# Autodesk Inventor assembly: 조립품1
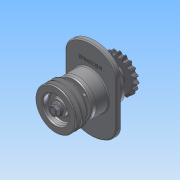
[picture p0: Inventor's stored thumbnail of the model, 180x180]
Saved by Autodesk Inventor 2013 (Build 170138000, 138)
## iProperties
Created: 2015-02
Part Number: 조립품1
Document SubType Name: Assembly
Designer: Administrator
Author: Administrator
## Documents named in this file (11)
- C:\Documents and Settings\Administrator\바탕 화면\새 폴더\조립품1.iam
- C:\Documents and Settings\Administrator\바탕 화면\새 폴더\1.본체.ipt
- C:\Documents and Settings\Administrator\바탕 화면\새 폴더\450207V1017\2-커버.ipt
- C:\Documents and Settings\Administrator\바탕 화면\새 폴더\450207V1017\3-축.ipt
- C:\Documents and Settings\Administrator\바탕 화면\새 폴더\450207V1017\5-체인 스프로킷.ipt
- C:\Documents and Settings\Administrator\바탕 화면\새 폴더\450207V1017\4-V벨트풀리.ipt
- C:\Documents and Settings\Administrator\바탕 화면\새 폴더\450207V1017\6-베어링 6206.ipt
- C:\Documents and Settings\Administrator\바탕 화면\새 폴더\450207V1017\7-부시.ipt
- C:\Documents and Settings\Administrator\바탕 화면\새 폴더\450207V1017\8-오일실 30x42.ipt
- C:\Documents and Settings\Administrator\바탕 화면\새 폴더\450207V1017\11-키 6x6.ipt
- C:\Documents and Settings\Administrator\바탕 화면\새 폴더\450207V1017\9-M16-너트.ipt
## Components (15 placed, 10 different names)
1. 1.본체:1
2. 2-커버:1
3. 2-커버:2
4. 3-축:1
5. 4-V벨트풀리:1 — 각도:2
6. 5-체인 스프로킷:1 — 각도:1
7. 6-베어링 6206:1
8. 6-베어링 6206:2
9. 7-부시:1
10. 8-8-오일실 30x42:1
11. 8-8-오일실 30x42:2
12. 11-키 6x6:1 — 각도:2
13. 11-키 6x6:2 — 각도:1
14. 9-M16 너트:1
15. 9-M16 너트:2
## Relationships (2: Angle 2)
- 각도:1 [Angle]: 5-체인 스프로킷:1 ↔ 11-키 6x6:2
- 각도:2 [Angle]: 4-V벨트풀리:1 ↔ 11-키 6x6:1
